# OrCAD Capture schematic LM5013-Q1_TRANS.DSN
size D; title: LM5013-Q1, 100-V Input, 3.5-A Non-Synchronous; rev: 1.0; note: Datasheet: SNVSBP5A      EVM:SNVU754A; note: Synchronous Step Down Converter; note: Buck DC/DC Converter with Ultra low IQ
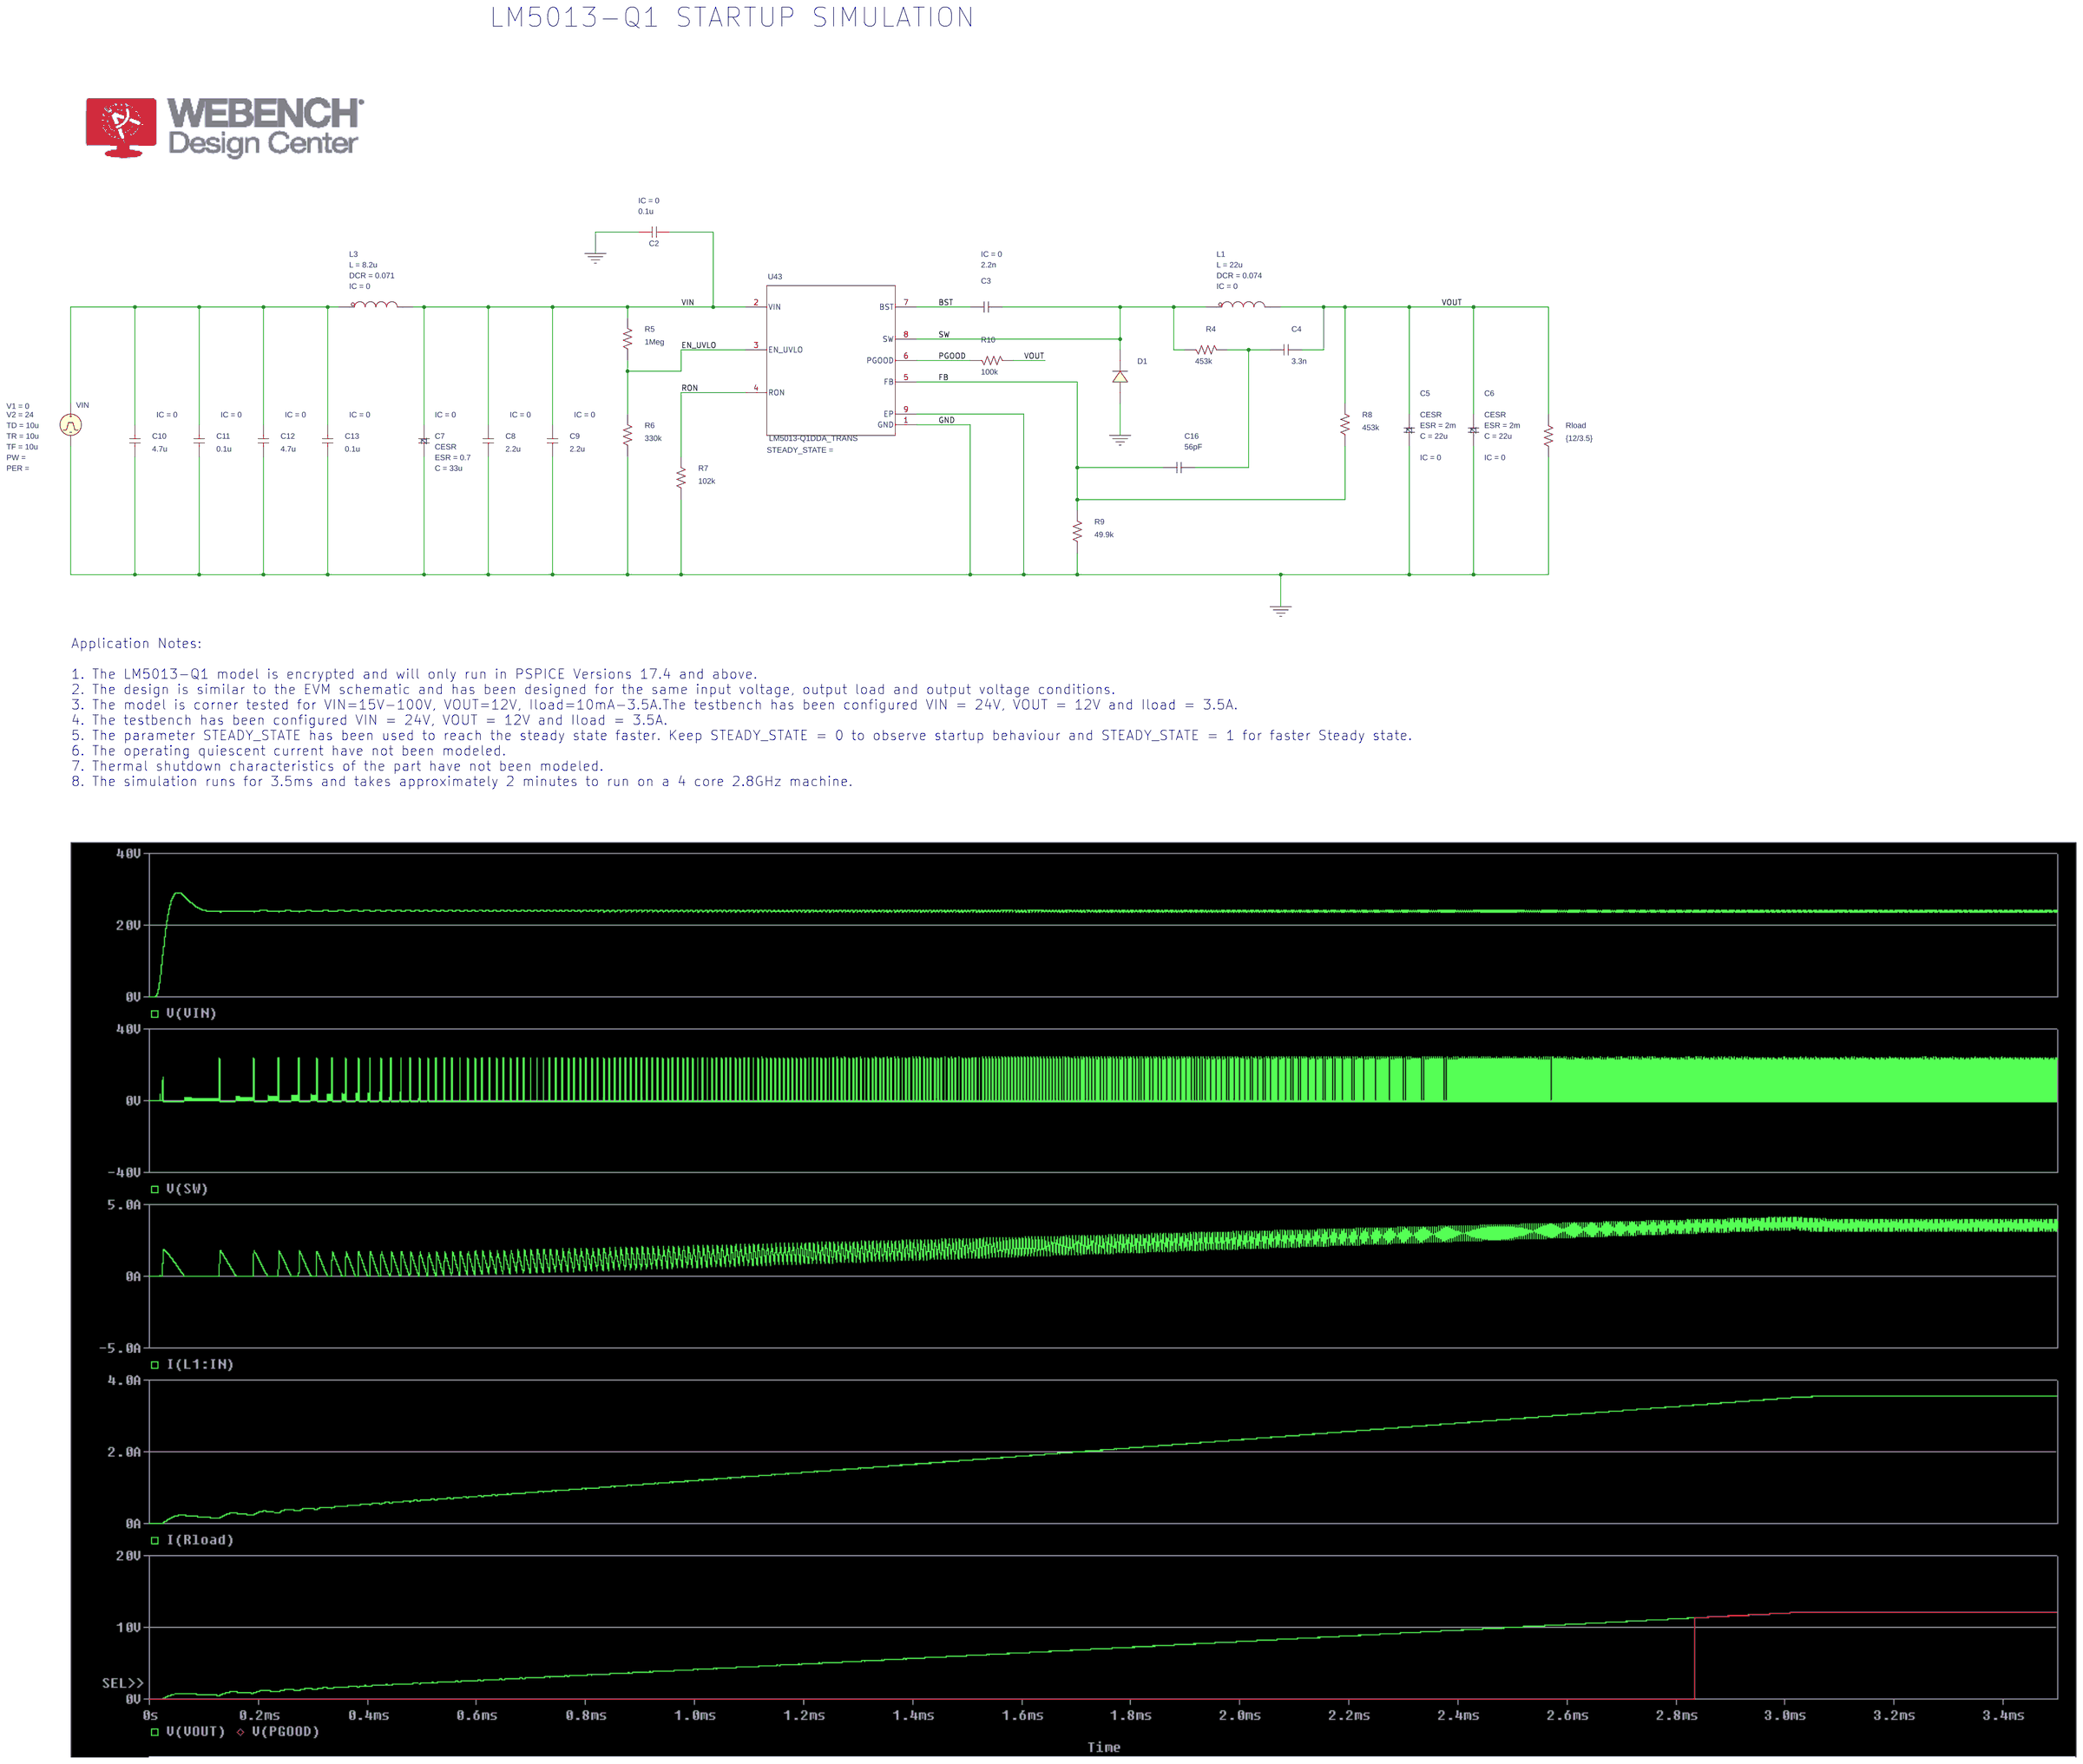
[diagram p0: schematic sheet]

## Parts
C2  0.1u  [RAD/CK05]
C3  2.2n  [RAD/CK05]
C4  3.3n  [RAD/CK05]
C5  CESR
C6  CESR
C7  CESR
C8  2.2u  [RAD/CK05]
C9  2.2u  [RAD/CK05]
C10  4.7u  [RAD/CK05]
C11  0.1u  [RAD/CK05]
C12  4.7u  [RAD/CK05]
C13  0.1u  [RAD/CK05]
C16  56pF  [RAD/CK05]
D1  D_D1
L1  LDCR
L3  LDCR
R4  453k  [AX/RC05]
R5  1Meg  [AX/RC05]
R6  330k  [AX/RC05]
R7  102k  [AX/RC05]
R8  453k  [AX/RC05]
R9  49.9k  [AX/RC05]
R10  100k  [AX/RC05]
Rload  {12/3.5}  [AX/RC05]
U43  LM5013-Q1DDA_TRANS  [DDA0008E-IPC_A]
VIN  VPULSE

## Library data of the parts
C2 C3 C8-C13 = C: IC: 0
C4 C16 = C
C5 = CESR_1: C: 22u; ESR: 2m; IC: 0; PSpiceTemplate: X^@REFDES %1 %2 @MODEL PARAMS: ?C|C=@C||C=10U| ?ESR|ESR=@ESR||ESR=2M| ?IC|IC=@IC||IC=1N| ?X|X=@X||X=1|; X: 1
C6 = CESR: C: 22u; ESR: 2m; IC: 0; PSpiceTemplate: X^@REFDES %1 %2 @MODEL PARAMS: ?C|C=@C||C=10U| ?ESR|ESR=@ESR||ESR=2M| ?IC|IC=@IC||IC=1N| ?X|X=@X||X=1|; X: 1
C7 = CESR_2: C: 33u; ESR: 0.7; IC: 0; PSpiceTemplate: X^@REFDES %1 %2 @MODEL PARAMS: ?C|C=@C||C=10U| ?ESR|ESR=@ESR||ESR=2M| ?IC|IC=@IC||IC=1N| ?X|X=@X||X=1|; X: 1
D1 = D_D1
L1 = LDCR_0: DCR: 0.074; IC: 0; L: 22u; PSpiceTemplate: X^@REFDES %IN %OUT @MODEL PARAMS:  ?L|L=@L||L=1u|  ?DCR|DCR=@DCR||DCR=0.01| ?IC|IC=@IC||IC=0|
L3 = LDCR_0: DCR: 0.071; IC: 0; L: 8.2u; PSpiceTemplate: X^@REFDES %IN %OUT @MODEL PARAMS:  ?L|L=@L||L=1u|  ?DCR|DCR=@DCR||DCR=0.01| ?IC|IC=@IC||IC=0|
R4-R10 Rload = R
U43 = LM5013-Q1DDA_TRANS
VIN = VPULSE: TD: 10u; TF: 10u; TR: 10u; V1: 0; V2: 24

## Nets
VIN: C2.2 C7.1 C8.1 C9.1 L3.3(OUT) R5.2 U43.2(VIN)
0: C2.1 C5.2 C6.2 C7.2 C8.2 C9.2 C10.2 C11.2 C12.2 C13.2 D1.1 R6.1 R7.1 R9.1 Rload.2 U43.1(GND) U43.9(EP) VIN.2(-)
BST: C3.2 U43.7(BST)
EN_UVLO: R5.1 R6.2 U43.3(EN_UVLO)
FB: C16.2 R8.1 R9.2 U43.5(FB)
PGOOD: R10.1 U43.6(PGOOD)
RON: R7.2 U43.4(RON)
SW: C3.1 D1.2 L1.1(IN) R4.1 U43.8(SW)
VOUT: C4.2 C5.1 C6.1 L1.3(OUT) R8.2 R10.2 Rload.1
N37411: C10.1 C11.1 C12.1 C13.1 L3.1(IN) VIN.1(+)
N37719: C4.1 C16.1 R4.2

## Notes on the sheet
- LM5013-Q1 STARTUP SIMULATION
- Application Notes:
  1. The LM5013-Q1 model is encrypted and will only run in PSPICE Versions 17.4 and above.
  2. The design is similar to the EVM schematic and has been designed for the same input voltage, output load and output voltage conditions.
  3. The model is corner tested for VIN=15V-100V, VOUT=12V, Iload=10mA-3.5A.The testbench has been configured VIN = 24V, VOUT = 12V and Iload = 3.5A.
  4. The testbench has been configured VIN = 24V, VOUT = 12V and Iload = 3.5A.
  5. The parameter STEADY_STATE has been used to reach the steady state faster. Keep STEADY_STATE = 0 to observe startup behaviour and STEADY_STATE = 1 for faster Steady state.
  6. The operating quiescent current have not been modeled.
  7. Thermal shutdown characteristics of the part have not been modeled.
  8. The simulation runs for 3.5ms and takes approximately 2 minutes to run on a 4 core 2.8GHz machine.
